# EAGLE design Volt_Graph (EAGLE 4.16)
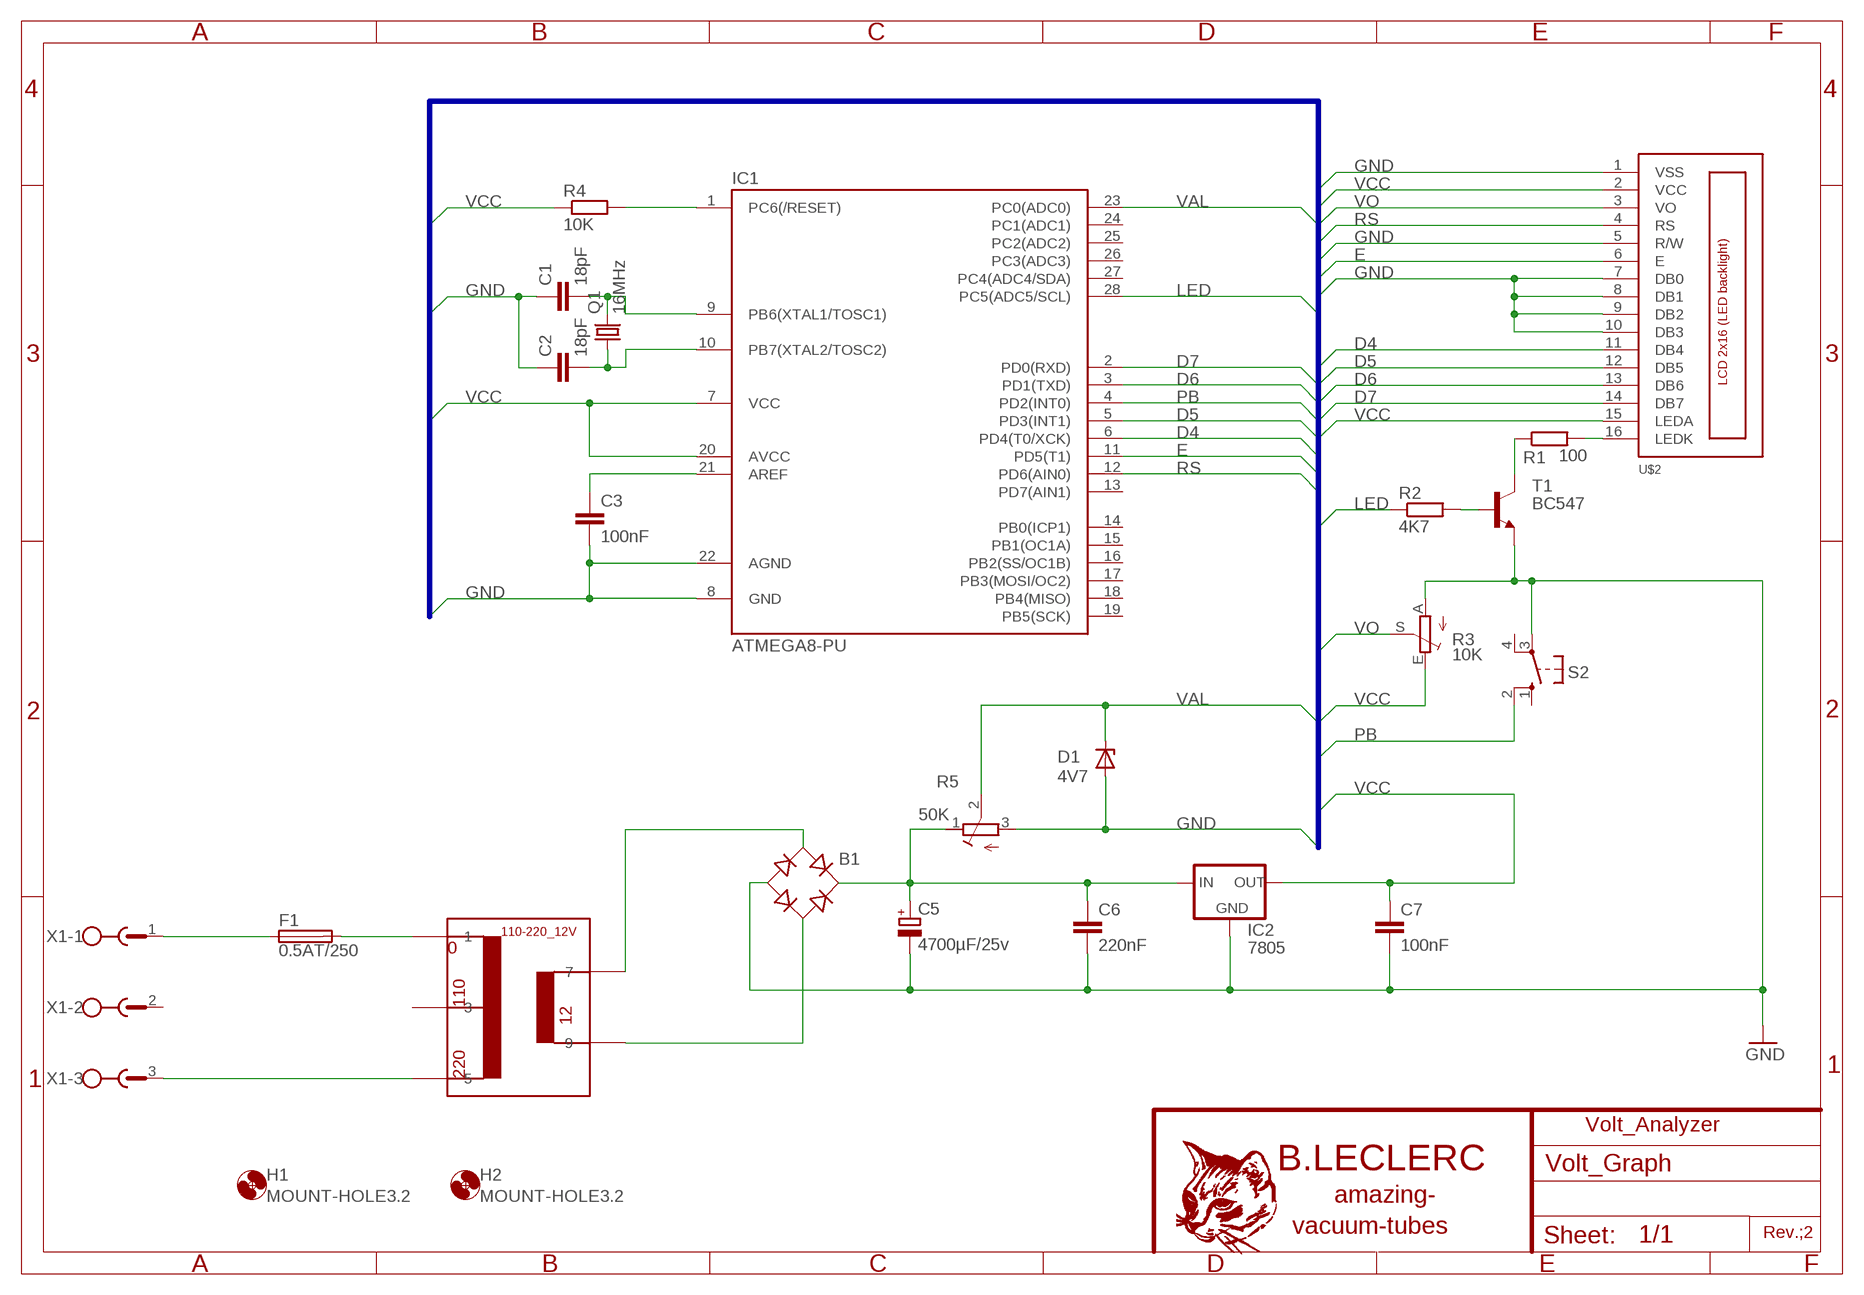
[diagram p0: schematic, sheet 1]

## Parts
B1  RB1A  [RB1A]
C1  18pF  C-EU025-025X050  [C025-025X050]
C2  18pF  C-EU025-025X050  [C025-025X050]
C3  100nF  C-EU025_050-025X075  [C025_050-025X075]
C5  4700µF/25v  CPOL-EUE7.5-16  [E7,5-16]
C6  220nF  C-EU025_050-035X075  [C025_050-035X075]
C7  100nF  C-EU025_050-035X075  [C025_050-035X075]
D1  4V7  ZENER-DIODEP1-12  [P1Z12]
F1  0.5AT/250  FUSESHK20L  [SHK20L]
H1  MOUNT-HOLE3.2  [3,2]
H2  MOUNT-HOLE3.2  [3,2]
IC1  ATMEGA8-PU  [DIL28-3]
IC2  7805  78XXS  [78XXS]
Q1  16MHz  CRYTALHC49S  [HC49/S]
R1  100  R-EU_0207/12  [0207/12]
R2  4K7  R-EU_0207/12  [0207/12]
R3  10K  TRIM_EU-LI10  [LI10]
R4  10K  R-EU_0207/12  [0207/12]
R5  50K  R-TRIMMT93YA  [RTRIMT93YA]
S2  10-XX  [B3F-10XX]
T1  BC547  [TO92]
U$2  LCD_4X20TOP  [LCD4_20]
U$3  110-220_12V  [110-220_12V]
X1  W232-3  [W232-3]

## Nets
D4: IC1.6(PD4(T0/XCK)) U$2.11(DB4)
D5: IC1.5(PD3(INT1)) U$2.12(DB5)
D6: IC1.3(PD1(TXD)) U$2.13(DB6)
D7: IC1.2(PD0(RXD)) U$2.14(DB7)
E: IC1.11(PD5(T1)) U$2.6(E)
GND: B1.- C1.1 C2.1 C3.2 C5.- C6.2 C7.2 D1.A IC1.8(GND) IC1.22(AGND) IC2.GND R3.A R5.3(E) S2.3(P) T1.1(E) U$2.1(VSS) U$2.5(R/W) U$2.7(DB0) U$2.8(DB1) U$2.9(DB2) U$2.10(DB3)
LED: IC1.28(PC5(ADC5/SCL)) R2.1
N$1: R1.2 U$2.16(LEDK)
N$2: R1.1 T1.3(C)
N$3: R2.2 T1.2(B)
N$4: IC1.1(PC6(/RESET)) R4.2
N$7: C1.2 IC1.9(PB6(XTAL1/TOSC1)) Q1.2
N$8: C2.2 IC1.10(PB7(XTAL2/TOSC2)) Q1.1
N$9: B1.AC2 U$3.9
N$10: C3.1 IC1.21(AREF)
N$11: B1.+ C5.+ C6.1 IC2.IN R5.1(A)
N$12: B1.AC1 U$3.7
N$15: F1.1A X1.1
N$16: U$3.5 X1.3
N$17: F1.2A U$3.1
PB: IC1.4(PD2(INT0)) S2.2(S1)
RS: IC1.12(PD6(AIN0)) U$2.4(RS)
VAL: D1.C IC1.23(PC0(ADC0)) R5.2(S)
VCC: C7.1 IC1.7(VCC) IC1.20(AVCC) IC2.OUT R3.E R4.1 U$2.2(VCC) U$2.15(LEDA)
VO: R3.S U$2.3(VO)
Unconnected: IC1.13(PD7(AIN1)) IC1.14(PB0(ICP1)) IC1.15(PB1(OC1A)) IC1.16(PB2(SS/OC1B)) IC1.17(PB3(MOSI/OC2)) IC1.18(PB4(MISO)) IC1.19(PB5(SCK)) IC1.24(PC1(ADC1)) IC1.25(PC2(ADC2)) IC1.26(PC3(ADC3)) IC1.27(PC4(ADC4/SDA)) S2.1(S) S2.4(P1) X1.2

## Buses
B$1

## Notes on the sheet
- Volt_Analyzer
- Rev.;2

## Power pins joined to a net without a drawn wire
3: U$3.3

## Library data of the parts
B1 = rectifier:RB1A: RECTIFIER 1 A
C1-C3 C6 C7 = rcl:C-EU: CAPACITOR, European symbol
C5 = rcl:CPOL-EU: POLARIZED CAPACITOR, European symbol
D1 = diode:ZENER-DIODE: Z-Diode
F1 = fuse:FUSE: Fuse
H1 H2 = holes:MOUNT-HOLE: MOUNTING HOLE with drill center marker
IC1 = atmega8:ATMEGA8-PU
IC2 = v-reg:78XXS: VOLTAGE REGULATOR
Q1 = crystal:CRYTAL: CRYSTAL
R1 R2 R4 = rcl:R-EU_: RESISTOR, European symbol
R3 = pot:TRIM_EU-: POTENTIOMETER
R5 = rcl:R-TRIMM: Trimm resistor
S2 = switch-omron:10-XX: OMRON SWITCH
T1 = transistor:BC547: NPN TRANSISTOR
U$2 = lcd_4x16_backlight:LCD_4X20TOP
U$3 = trafo:110-220_12V
X1 = con-wago-508:W232-3: WAGO SREW CLAMP

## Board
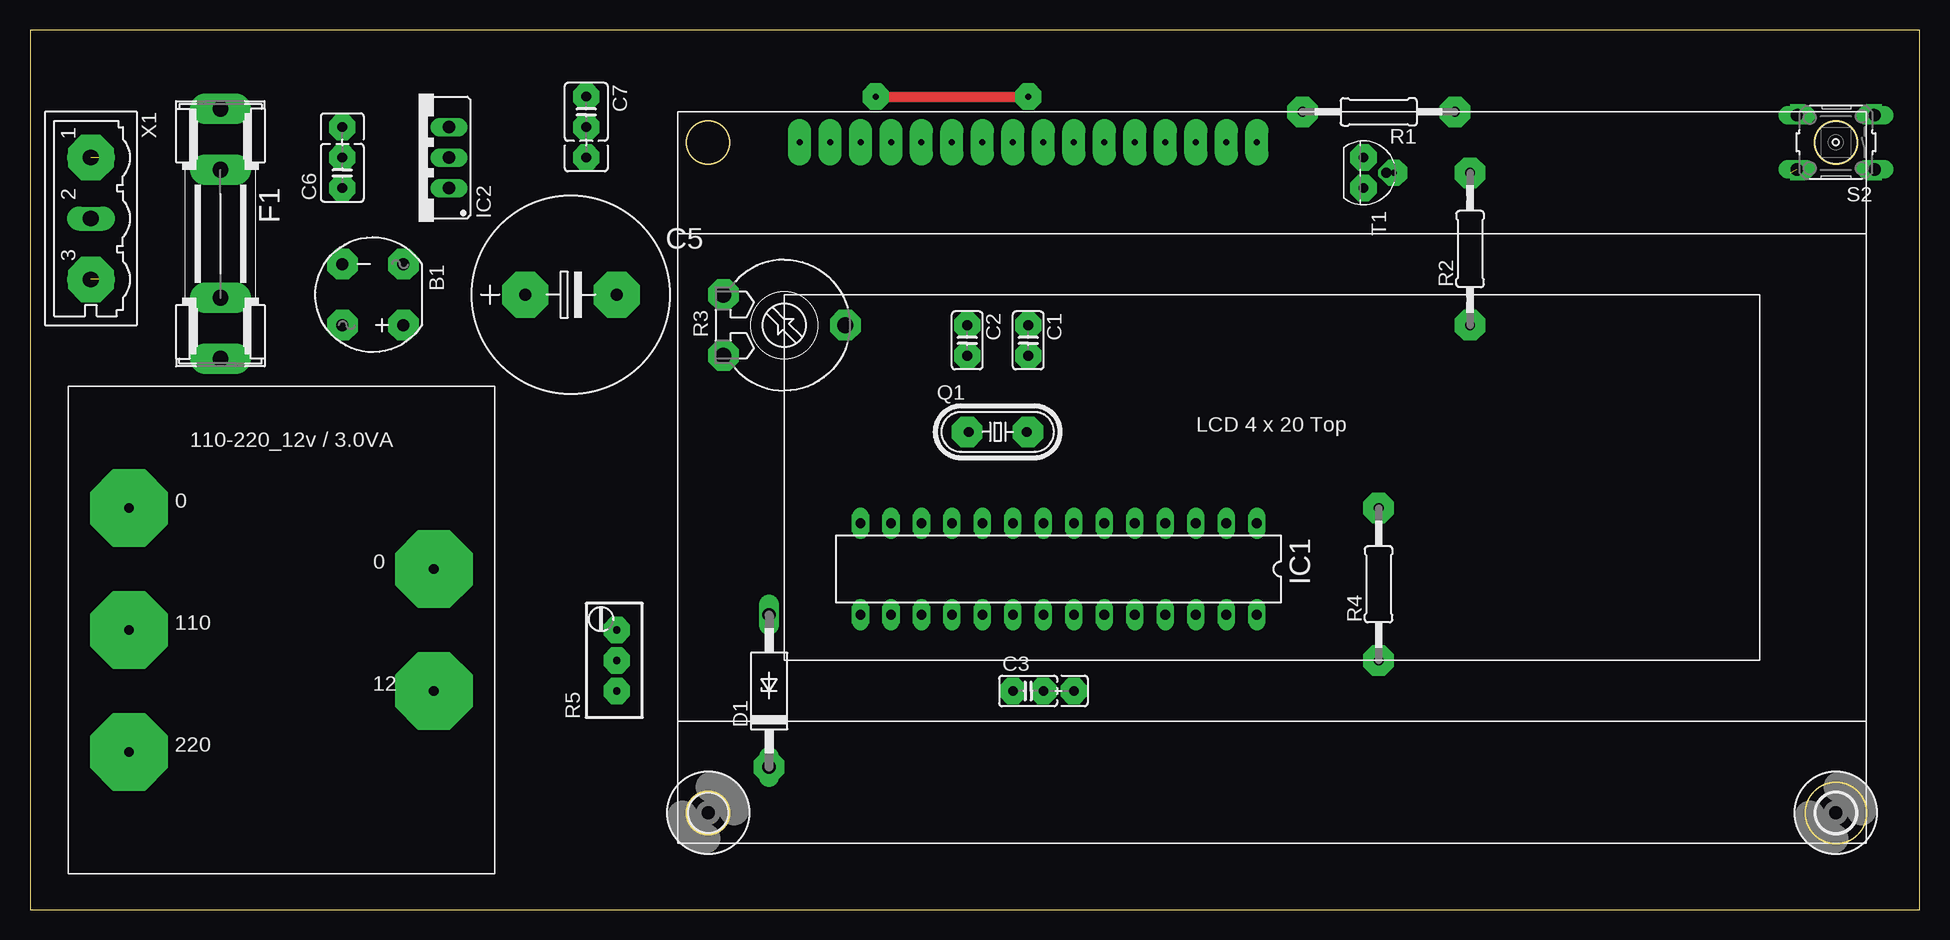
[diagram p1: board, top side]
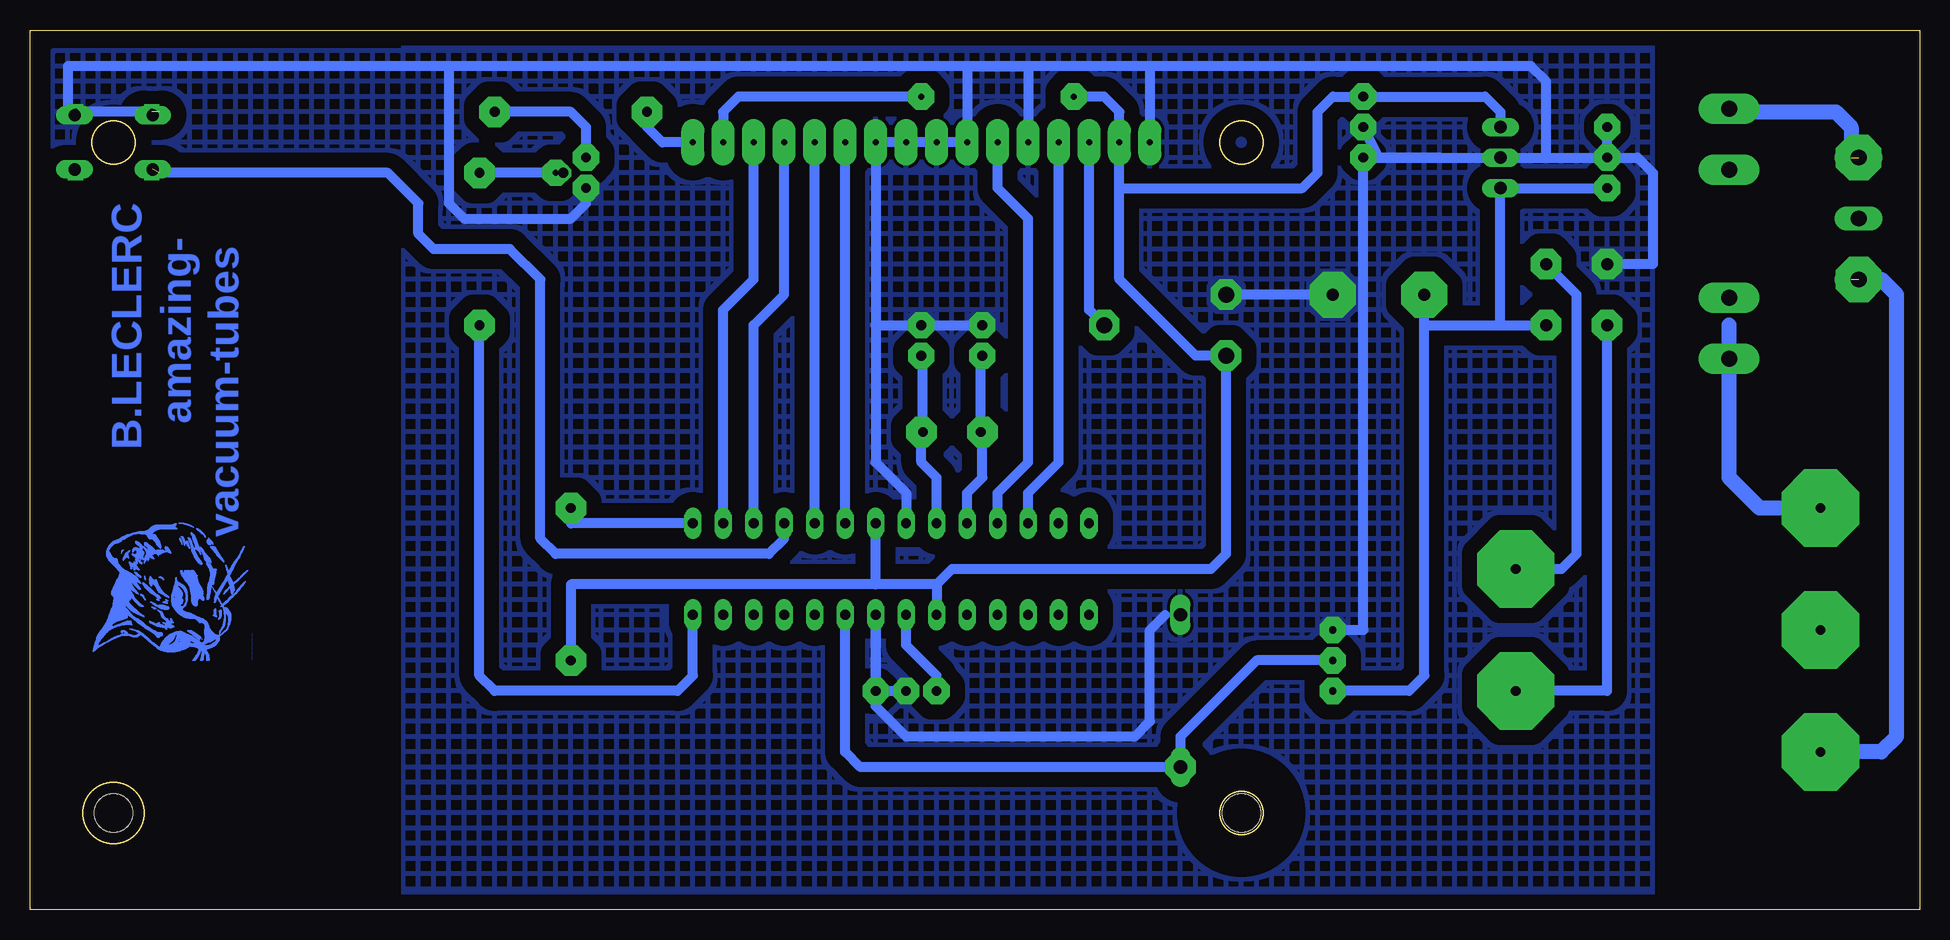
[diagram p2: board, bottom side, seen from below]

Size 157.46 x 73.33 mm. Coordinates in mm from the lower left corner, seen from the top.
Outline: 0,0 157.46,0 157.46,73.33 0,73.33 0,0
Copper layers (1*16): Top 0.035mm / dielectric 1.5mm / Bottom 0.035mm
Design rules "default": minimum track width 10mil, minimum drill 24mil, track to track 8mil, track to pad 8mil, pad to pad 8mil, via to via 8mil, smd to smd 8mil, copper to edge 40mil, drill to drill 8mil, minimum pad ring 10mil, minimum via ring 8mil, stop-mask expansion 4mil, vias tented up to drill 0mil, thermal gap 10mil

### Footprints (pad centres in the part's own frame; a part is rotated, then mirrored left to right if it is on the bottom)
RB1A = drill 1.016 round: + -2.54,2.54 | drill 1.016 octagon: - 2.54,-2.54; AC1 2.54,2.54; AC2 -2.54,-2.54
C025-025X050 = drill 0.813 octagon: 1 -1.27,0; 2 1.27,0
C025_050-025X075 = drill 0.813 octagon: 1 -1.27,0; 2 1.27,0; 3 3.81,0
E7,5-16 = drill 1.016 pad 3.15 round: + -3.81,0 | drill 1.016 pad 3.15 octagon: - 3.81,0
C025_050-035X075 = drill 0.813 octagon: 1 -1.27,0; 2 1.27,0; 3 3.81,0
P1Z12 = drill 1.118 long: A 6.35,0; C -6.35,0
SHK20L = drill 1.321 pad 2.54 long: 1A -10.414,0; 1B -5.334,0; 2A 10.414,0; 2B 5.334,0
3,2 = hole 3.2: 0,0
DIL28-3 = drill 0.813 long: 1 -16.51,-3.81; 2 -13.97,-3.81; 3 -11.43,-3.81; 4 -8.89,-3.81; 5 -6.35,-3.81; 6 -3.81,-3.81; 7 -1.27,-3.81; 8 1.27,-3.81; 9 3.81,-3.81; 10 6.35,-3.81; 11 8.89,-3.81; 12 11.43,-3.81; 13 13.97,-3.81; 14 16.51,-3.81; 15 16.51,3.81; 16 13.97,3.81; 17 11.43,3.81; 18 8.89,3.81; 19 6.35,3.81; 20 3.81,3.81; 21 1.27,3.81; 22 -1.27,3.81; 23 -3.81,3.81; 24 -6.35,3.81; 25 -8.89,3.81; 26 -11.43,3.81; 27 -13.97,3.81; 28 -16.51,3.81
78XXS = drill 1.016 long: GND 0,-2.54; IN -2.54,-2.54; OUT 2.54,-2.54
HC49/S = drill 0.813 round: 1 -2.413,0; 2 2.413,0
0207/12 = drill 0.813 octagon: 1 -6.35,0; 2 6.35,0
LI10 = drill 1.321 octagon: A -2.54,-5.08; E 2.54,-5.08; S 0,5.08
RTRIMT93YA = drill 0.61 round: 1 0,-2.54; 2 0,0; 3 0,2.54
B3F-10XX = drill 1.016 long: 1 -3.251,2.261; 2 3.251,2.261; 3 -3.251,-2.261; 4 3.251,-2.261
TO92 = drill 0.813 octagon: 1 1.27,0; 2 0,1.905; 3 -1.27,0
LCD4_20 = drill 0.5 pad 1.93 long: 1 -39.37,27.94; 2 -36.83,27.94; 3 -34.29,27.94; 4 -31.75,27.94; 5 -29.21,27.94; 6 -26.67,27.94; 7 -24.13,27.94; 8 -21.59,27.94; 9 -19.05,27.94; 10 -16.51,27.94; 11 -13.97,27.94; 12 -11.43,27.94; 13 -8.89,27.94; 14 -6.35,27.94; 15 -3.81,27.94; 16 -1.27,27.94
110-220_12V = drill 0.8 pad 3.81 octagon: 1 -12.7,10.16; 3 -12.7,0; 5 -12.7,-10.16; 7 12.7,-5.08; 9 12.7,5.08
W232-3 = drill 1.321 long: 1 -5.08,-0.635; 2 0,-0.635; 3 5.08,-0.635

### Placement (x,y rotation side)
B1  28.57,51.27 180 top
C1  83.18,47.46 270 top
C2  78.1,47.46 270 top
C3  83.18,18.25 0 top
C5  45.08,51.27 0 top
C6  26.03,61.43 90 top
C7  46.35,66.51 270 top
D1  61.59,18.25 90 top
F1  15.87,56.35 270 top
H1  150.49,8.09 0 top
H2  56.51,8.09 0 top
IC1  85.72,28.41 180 top
IC2  32.38,62.7 90 top
Q1  80.64,39.84 0 top
R1  112.39,66.51 180 top
R2  120.01,55.08 90 top
R3  62.86,48.73 270 top
R4  112.39,27.14 90 top
R5  48.89,20.79 0 top
S2  150.49,63.97 180 top
T1  111.12,61.43 270 top
U$2  103.5,36.03 0 top
U$3  20.95,23.33 0 top
U$4  [CHAT1]  139.06,20.79 90 bottom
X1  5.71,57.62 270 top

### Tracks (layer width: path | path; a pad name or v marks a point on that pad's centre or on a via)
D4
  Bottom 0.813: IC1.6 U$2.11
D5
  Bottom 0.813: IC1.5 U$2.12
D6
  Bottom 0.813: U$2.13 94.61,51.27 97.15,48.73 IC1.3
D7
  Bottom 0.813: U$2.14 97.15,52.54 99.69,50 IC1.2
E
  Bottom 0.813: IC1.11 76.83,34.76 74.29,37.3 74.29,57.62 76.83,60.16 U$2.6
GND  (via drill 0.5 pad 1.27, 0.5 pad 2.18, 0.5 pad 2.54, 0.5 pad 3.81)  (1 unrouted)
  Bottom 0.813: C2.1 C1.1 86.99,48.73 | IC1.8 84.45,34.76 86.99,37.3 86.99,48.73 | 86.99,48.73 U$2.10 U$2.9 U$2.8 U$2.7 79.37,70.32 | 79.37,70.32 74.29,70.32 U$2.5 | 31.11,62.7 C6.2 | 31.11,62.7 IC2.GND 40,62.7 | 40,62.7 45.08,62.7 C7.2 | 64.13,70.32 U$2.1 | 64.13,70.32 32.38,70.32 31.11,69.05 31.11,62.7 | 40,62.7 v46.35,62.7 46.35,23.33 R5.3 | C5.- R3.A | C3.2 v86.99,18.25 IC1.22 86.99,16.98 84.45,14.44 65.4,14.44 64.13,15.71 64.13,23.33 62.86,24.6 | T1.1 111.12,58.89 112.39,57.62 121.28,57.62 122.55,58.89 122.55,70.32 | 64.13,70.32 79.37,70.32 | 79.37,70.32 122.55,70.32 | C6.2 23.49,62.7 22.22,61.43 22.22,53.81 B1.- | C6.2 v26.03,65.24 | S2.3 154.3,66.23 154.3,70.32 122.55,70.32 | 146.68,66.51 v153.66,66.51
  other vias: 26.03,62.7 26.03,53.81 46.35,65.24 48.89,51.27 57.78,51.27 111.12,60.16 78.1,48.73 83.18,48.73 84.45,18.25 48.89,23.33 147.31,66.51
  pour Bottom (isolate 1.27, hatched): 22.22,72.86 126.36,72.86 126.36,6.82 126.36,0.47 22.22,0.47
  pour Bottom (isolate 1.27, no thermals, hatched): 126.36,71.59 155.57,71.59 155.57,58.89 126.36,58.89 126.36,70.32
LED
  Bottom 0.813: R2.1 120.01,19.52 118.74,18.25 103.5,18.25 102.23,19.52 IC1.28
N$1
  Bottom 0.813: U$2.16 104.77,63.97 106.04,65.24 R1.2
N$2
  Bottom 0.813: R1.1 112.39,66.51 111.12,65.24 T1.3
N$3
  Bottom 0.813: T1.2 R2.2
N$4
  Bottom 0.813: IC1.1 112.39,32.22 R4.2
N$5  (via drill 0.6 pad 3.81)
  other vias: 5.08,52.54
N$6  (via drill 0.6 pad 3.81)
  other vias: 5.08,62.7
N$7
  Bottom 0.813: C1.2 83.05,46.06 Q1.2 83.18,39.84 83.18,37.3 81.91,36.03 IC1.9
N$8
  Bottom 0.813: C2.2 78.23,46.06 Q1.1 78.1,39.84 78.1,36.03 79.37,34.76 IC1.10
N$9
  Bottom 0.813: B1.AC2 28.57,51.27 28.57,29.68 29.84,28.41 U$3.9
N$10
  Bottom 0.813: IC1.21 84.45,22.06 81.91,19.52 C3.1
N$11
  Bottom 0.813: 34.92,48.73 B1.+ | 34.92,48.73 IC2.IN C6.1 | 41.27,48.73 C5.+ | 41.27,48.73 34.92,48.73 | 41.27,48.73 41.27,19.52 42.54,18.25 R5.1
N$12
  Bottom 0.813: B1.AC1 26.03,18.25 U$3.7
N$14  (via drill 0.5 pad 6.45)
  other vias: 8.25,23.33
N$15  (1 unrouted)
  Bottom 1.27: F1.1A 15.87,66.51 6.98,66.51 5.71,65.24 5.71,62.7
N$16  (1 unrouted)
  Bottom 1.27: U$3.5 3.17,13.17 1.9,14.44 1.9,51.27 3.17,52.54 5.71,52.54
N$17
  Bottom 1.27: U$3.1 13.33,33.49 15.87,36.03 F1.2A 15.87,48.73
N$18  (via drill 0.5 pad 6.45)
  other vias: 8.25,13.17
N$19  (via drill 0.5 pad 6.45)
  other vias: 33.65,18.25
N$20  (via drill 0.5 pad 6.45)
  other vias: 33.65,28.41
N$21  (via drill 0.5 pad 6.45)
  other vias: 8.25,33.49
N$24  (via drill 0.5 pad 2.18)
  other vias: 26.03,60.16
N$25  (via drill 0.5 pad 2.18)
  other vias: 46.35,67.78
N$26  (via drill 0.5 pad 1.27)
  other vias: 153.66,61.43
N$27  (via drill 0.5 pad 1.27)
  other vias: 147.31,61.43
N$28  (via drill 0.5 pad 2.18)
  other vias: 70.48,67.78
N$29  (via drill 0.5 pad 2.18)
  other vias: 111.12,62.7
N$30  (via drill 0.5 pad 2.18)
  other vias: 113.66,61.43
N$31  (via drill 0.5 pad 2.18)
  other vias: 83.18,67.78
N$32  (via drill 0.5 pad 2.18)
  other vias: 78.1,46.19
N$34  (via drill 0.5 pad 2.18)
  other vias: 81.91,18.25
N$37  (via drill 0.5 pad 2.18)
  other vias: 83.18,46.19
N$38  (via drill 0.5 pad 2.18)
  other vias: 48.89,18.25
N$39  (via drill 0.5 pad 2.18)
  other vias: 48.89,20.79
N$43  (via drill 0.5 pad 2.54)
  other vias: 118.74,66.51
N$44  (via drill 0.5 pad 2.54)
  other vias: 106.04,66.51
N$45  (via drill 0.5 pad 2.54)
  other vias: 120.01,61.43
N$46  (via drill 0.5 pad 2.54)
  other vias: 120.01,48.73
N$47  (via drill 0.5 pad 2.54)
  other vias: 112.39,33.49
N$48  (via drill 0.5 pad 2.54)
  other vias: 112.39,20.79
N$49  (via drill 0.5 pad 2.54)
  other vias: 61.59,11.9
N$54  (via drill 0.5 pad 2.54)
  other vias: 31.11,53.81
N$55  (via drill 0.5 pad 2.54)
  other vias: 31.11,48.73
N$56  (via drill 0.5 pad 2.54)
  other vias: 26.03,48.73
N$57  (via drill 0.5 pad 2.54)
  other vias: 78.1,39.84
N$58  (via drill 0.5 pad 2.54)
  other vias: 83.18,39.84
N$60  (via drill 0.5 pad 3.81)
  other vias: 41.27,51.27
N$61  (via drill 0.5 pad 2.54)
  other vias: 67.94,48.73
N$63  (via drill 0.5 pad 2.54)
  other vias: 57.78,46.19
N$64  (via drill 0.5 pad 1.42)
  other vias: 76.83,32.22
N$65  (via drill 0.5 pad 1.42)
  other vias: 79.37,32.22
N$66  (via drill 0.5 pad 1.42)
  other vias: 81.91,32.22
N$67  (via drill 0.5 pad 1.42)
  other vias: 89.53,32.22
N$68  (via drill 0.5 pad 1.42)
  other vias: 92.07,32.22
N$69  (via drill 0.5 pad 1.42)
  other vias: 94.61,32.22
N$70  (via drill 0.5 pad 1.42)
  other vias: 74.29,32.22
N$71  (via drill 0.5 pad 1.42)
  other vias: 71.75,32.22
N$72  (via drill 0.5 pad 1.42)
  other vias: 86.99,32.22
N$73  (via drill 0.5 pad 1.42)
  other vias: 84.45,32.22
N$74  (via drill 0.5 pad 1.42)
  other vias: 74.29,24.6
N$75  (via drill 0.5 pad 1.42)
  other vias: 79.37,24.6
N$76  (via drill 0.5 pad 1.42)
  other vias: 84.45,24.6
N$77  (via drill 0.5 pad 1.42)
  other vias: 89.53,24.6
N$78  (via drill 0.5 pad 1.42)
  other vias: 97.15,24.6
N$79  (via drill 0.5 pad 1.42)
  other vias: 69.21,32.22
N$80  (via drill 0.5 pad 1.42)
  other vias: 71.75,24.6
N$81  (via drill 0.5 pad 1.42)
  other vias: 69.21,24.6
N$82  (via drill 0.5 pad 1.42)
  other vias: 102.23,24.6
N$83  (via drill 0.5 pad 1.42)
  other vias: 99.69,24.6
N$84  (via drill 0.5 pad 1.42)
  other vias: 94.61,24.6
N$85  (via drill 0.5 pad 1.42)
  other vias: 92.07,24.6
N$86  (via drill 0.5 pad 1.42)
  other vias: 86.99,24.6
N$87  (via drill 0.5 pad 1.42)
  other vias: 81.91,24.6
N$88  (via drill 0.5 pad 1.42)
  other vias: 76.83,24.6
N$89  (via drill 0.5 pad 1.42)
  other vias: 102.23,32.22
N$90  (via drill 0.5 pad 1.42)
  other vias: 99.69,32.22
N$91  (via drill 0.5 pad 1.42)
  other vias: 97.15,32.22
PB  (1 unrouted)
  Bottom 0.813: IC1.4 94.61,30.95 95.88,29.68 113.66,29.68 114.93,30.95 114.93,52.54 117.47,55.08 123.82,55.08 125.09,56.35 125.09,58.89 127.63,61.43 146.68,61.43
RS
  Bottom 0.813: U$2.4 71.75,37.3 74.29,34.76 IC1.12
VAL
  Bottom 0.813: IC1.23 89.53,13.17 88.26,11.9 D1.C 61.59,14.44 55.24,20.79 R5.2
VCC  (via drill 0.5 pad 2.18)
  Top 0.813: v70.48,67.78 v83.18,67.78
  Bottom 0.813: 66.67,60.16 66.67,52.54 60.32,46.19 R3.E 57.78,29.68 59.05,28.41 80.64,28.41 81.91,27.14 | 66.67,60.16 U$2.2 66.67,66.51 67.94,67.78 v70.48,67.78 | 81.91,27.14 86.99,27.14 | 86.99,27.14 112.39,27.14 R4.1 | 86.99,27.14 IC1.7 | 81.91,27.14 IC1.20 | 66.67,60.16 51.43,60.16 50.16,61.43 50.16,66.51 48.89,67.78 C7.1 36.19,67.78 34.92,66.51 IC2.OUT | U$2.15 99.69,66.51 98.42,67.78 v83.18,67.78
VO
  Bottom 0.813: U$2.3 69.21,50 R3.S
